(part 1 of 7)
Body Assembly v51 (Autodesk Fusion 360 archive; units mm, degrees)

design "half proto board"
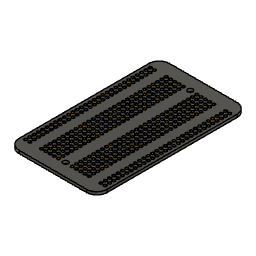
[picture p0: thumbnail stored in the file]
sketch "Sketch1" plane through (0, 0, 0) normal (0, 0, 1) x axis (1, 0, 0)
  line L1 (-26.05, -44.5) -> (26.05, -44.5)
  line L2 (-26.05, 44.5) -> (-26.05, -44.5)
  line L3 (26.05, 44.5) -> (-26.05, 44.5)
  line L4 (26.05, -44.5) -> (26.05, 44.5)
  line L5 (-26.05, 44.5) -> (26.05, -44.5)
  line L6 (26.05, 44.5) -> (-26.05, -44.5)
  line L7 (0, 44.5) -> (0, -44.5)
  line L8 (26.05, 0) -> (0, 0)
  line L9 (23.55, 44.5) -> (23.55, -44.5)
  line L10 (21.05, 44.5) -> (21.05, -44.5)
  line L11 (14.05, 44.5) -> (14.05, -44.5)
  circle C1 centre (0, -36.85) radius 1.5
  circle C2 centre (0, 36.85) radius 1.5
  circle C3 centre (23.55, -37) radius 0.65
  circle C4 centre (21.05, -37) radius 0.65
  circle C5 centre (21.05, -37) radius 0.85
  circle C6 centre (23.55, -37) radius 0.85
  circle C7 centre (14.05, -37) radius 0.65
  circle C8 centre (14.05, -37) radius 0.85
  point P6 (0, 0)
  point P1 (0, 0)
  point P7 (0, -44.5)
  point P8 (0, 44.5)
  point P9 (0, -36.85)
  point P10 (0, 0)
  point P11 (26.05, 0)
  point P13 (23.55, -44.5)
  point P14 (23.55, 44.5)
  point P15 (21.05, -44.5)
  point P16 (21.05, 44.5)
  point P17 (14.05, -44.5)
  point P18 (14.05, 44.5)
  point P19 (23.55, -37)
  point P20 (21.05, -37)
  point P23 (14.05, -37)
  point P2 (26.05, -44.5)
  point P5 (26.05, 44.5)
  horizontal L1
  perpendicular L1 L2
  parallel L1 L3
  parallel L2 L4
  coincident L5 P6
  coincident L6 P6
  coincident P1 P6
  midpoint L1 P7
  midpoint L3 P8
  coincident L7 P9
  coincident P1 P10
  midpoint L4 P11
  symmetric C1 L8 C2
  coincident L1 P13
  coincident L3 P14
  perpendicular L3 L9
  coincident L1 P15
  coincident L3 P16
  perpendicular L3 L10
  coincident L1 P17
  coincident L3 P18
  perpendicular L3 L11
  coincident L9 P19
  coincident L10 P20
  coincident L11 P23
  dimension "d1" distance P2 P5 = 89
  dimension "d2" distance L2 L4 = 52.1
  dimension "d3" diameter C1 = 3
  dimension "d4" distance P7 P9 = 7.65
  dimension "d9" distance L4 L9 = 2.5
  dimension "d10" distance L4 L10 = 5
  dimension "d11" distance L1 P20 = 7.5
  dimension "d12" distance L1 P19 = 7.5
  dimension "d13" diameter C3 = 1.3
  dimension "d14" diameter C4 = 1.3
  dimension "d15" = 0.2
  dimension "d16" = 0.2
  dimension "d17" distance L4 L11 = 12
  dimension "d18" diameter C7 = 1.3
  dimension "d19" = 0.2
  dimension "d20" distance L1 P23 = 7.5
extrude "Extrude1" new body sketch "Sketch1" profile of L1 L2 L3 L4 C1 C2 C3 C4 C5 C6 C7 C8 against normal blind 1.65
fillet "Fillet1" radius 6.1
extrude "Extrude2" cut sketch "Sketch1" profile of C3 C4 C5 C6 C7 C8 against normal blind 4
extrude "Extrude3" new body sketch "Sketch1" profile of C3 C4 C5 C6 C7 C8 against normal blind 1.65
rectangular_pattern "R-Pattern1" uSpaceDistance 2.5 vSpaceDistance 0
rectangular_pattern "R-Pattern2" uSpaceDistance -2.5 vSpaceDistance 0
copy_paste_bodies "CutPasteBodies1"
rectangular_pattern "R-Pattern3" countU 30 uSpaceDistance 73.7 vSpaceDistance 0
split "Split1"
remove_body "RemoveBody8"
mirror "Mirror1" mirrorStitchTolerance 0.1
rectangular_pattern "R-Pattern2" countU 30 uSpaceDistance -73.7 vSpaceDistance 0
mirror "Mirror1" mirrorStitchTolerance 0.1
component_from_bodies "Body->Comp1"
copy_paste "CutPaste"
component_from_bodies "Body->Comp1"
copy_paste_bodies "CutPasteBodies1"
as_built_joint "As-built1"
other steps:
base_feature "Base Feature1"
base_feature "Base Feature1"
base_feature "Base Feature1"
base_feature "Base Feature2"
create_component "CreateComponent1"
remove_body "RemoveBody1"
remove_body "RemoveBody2"
remove_body "RemoveBody3"
remove_body "RemoveBody4"
remove_body "RemoveBody5"
remove_body "RemoveBody6"
remove_body "RemoveBody7"
create_component "CreateComponent2"
remove_body "RemoveBody9"
remove_instance "RemoveInstance1"
create_component "CreateComponent1"
remove_body "RemoveBody1"
remove_body "RemoveBody2"
remove_body "RemoveBody3"
remove_body "RemoveBody4"
remove_body "RemoveBody5"
remove_body "RemoveBody6"
remove_body "RemoveBody7"
remove_body "RemoveBody8"
remove_body "RemoveBody9"
remove_body "RemoveBody10"
remove_body "RemoveBody11"
remove_body "RemoveBody12"
remove_body "RemoveBody13"
remove_body "RemoveBody14"
remove_body "RemoveBody15"
remove_body "RemoveBody16"
remove_body "RemoveBody17"
remove_body "RemoveBody18"
remove_body "RemoveBody19"
remove_body "RemoveBody20"
remove_body "RemoveBody21"
remove_body "RemoveBody22"
remove_body "RemoveBody23"
remove_body "RemoveBody24"
remove_body "RemoveBody25"
remove_body "RemoveBody26"
remove_body "RemoveBody27"
remove_body "RemoveBody28"
remove_body "RemoveBody29"
remove_body "RemoveBody30"
remove_body "RemoveBody31"
remove_body "RemoveBody32"
remove_body "RemoveBody33"
remove_body "RemoveBody34"
remove_body "RemoveBody35"
remove_body "RemoveBody36"
remove_body "RemoveBody37"
remove_body "RemoveBody38"
remove_body "RemoveBody39"
remove_body "RemoveBody40"
remove_body "RemoveBody41"
remove_body "RemoveBody42"
remove_body "RemoveBody43"
remove_body "RemoveBody44"
remove_body "RemoveBody45"
remove_body "RemoveBody46"
remove_body "RemoveBody47"
remove_body "RemoveBody48"
remove_body "RemoveBody49"
remove_body "RemoveBody50"
remove_body "RemoveBody51"
remove_body "RemoveBody52"
remove_body "RemoveBody53"
remove_body "RemoveBody54"
remove_body "RemoveBody55"
remove_body "RemoveBody56"
remove_body "RemoveBody57"
remove_body "RemoveBody58"
remove_body "RemoveBody59"
remove_body "RemoveBody60"
remove_body "RemoveBody61"
remove_body "RemoveBody62"
remove_body "RemoveBody63"
remove_body "RemoveBody64"
remove_body "RemoveBody65"
remove_body "RemoveBody66"
remove_body "RemoveBody67"
remove_body "RemoveBody68"
remove_body "RemoveBody69"
remove_body "RemoveBody70"
remove_body "RemoveBody71"
remove_body "RemoveBody72"
remove_body "RemoveBody73"
remove_body "RemoveBody74"
remove_body "RemoveBody75"
remove_body "RemoveBody76"
remove_body "RemoveBody77"
remove_body "RemoveBody78"
remove_body "RemoveBody79"
remove_body "RemoveBody80"
remove_body "RemoveBody81"
remove_body "RemoveBody82"
remove_body "RemoveBody83"
remove_body "RemoveBody84"
remove_body "RemoveBody85"
remove_body "RemoveBody86"
remove_body "RemoveBody87"
remove_body "RemoveBody88"
remove_body "RemoveBody89"
remove_body "RemoveBody90"
remove_body "RemoveBody91"
remove_body "RemoveBody92"
remove_body "RemoveBody93"
remove_body "RemoveBody94"
remove_body "RemoveBody95"
remove_body "RemoveBody96"
remove_body "RemoveBody97"
remove_body "RemoveBody98"
remove_body "RemoveBody99"
remove_body "RemoveBody100"
remove_body "RemoveBody101"
remove_body "RemoveBody102"
remove_body "RemoveBody103"
remove_body "RemoveBody104"
remove_body "RemoveBody105"
remove_body "RemoveBody106"
remove_body "RemoveBody107"
remove_body "RemoveBody108"
remove_body "RemoveBody109"
remove_body "RemoveBody110"
remove_body "RemoveBody111"
remove_body "RemoveBody112"
remove_body "RemoveBody113"
remove_body "RemoveBody114"
remove_body "RemoveBody115"
remove_body "RemoveBody116"
remove_body "RemoveBody117"
remove_body "RemoveBody118"
remove_body "RemoveBody119"
remove_body "RemoveBody120"
remove_body "RemoveBody121"
remove_body "RemoveBody122"
remove_body "RemoveBody123"
remove_body "RemoveBody124"
remove_body "RemoveBody125"
remove_body "RemoveBody126"
remove_body "RemoveBody127"
remove_body "RemoveBody128"
remove_body "RemoveBody129"
remove_body "RemoveBody130"
remove_body "RemoveBody131"
remove_body "RemoveBody132"
remove_body "RemoveBody133"
remove_body "RemoveBody134"
remove_body "RemoveBody135"
remove_body "RemoveBody136"
remove_body "RemoveBody137"
remove_body "RemoveBody138"
remove_body "RemoveBody139"
remove_body "RemoveBody140"
remove_body "RemoveBody141"
remove_body "RemoveBody142"
remove_body "RemoveBody143"
remove_body "RemoveBody144"
remove_body "RemoveBody145"
remove_body "RemoveBody146"
remove_body "RemoveBody147"
remove_body "RemoveBody148"
remove_body "RemoveBody149"
remove_body "RemoveBody150"
remove_body "RemoveBody151"
remove_body "RemoveBody152"
remove_body "RemoveBody153"
remove_body "RemoveBody154"
remove_body "RemoveBody155"
remove_body "RemoveBody156"
remove_body "RemoveBody157"
remove_body "RemoveBody158"
remove_body "RemoveBody159"
remove_body "RemoveBody160"
remove_body "RemoveBody161"
remove_body "RemoveBody162"
remove_body "RemoveBody163"
remove_body "RemoveBody164"
remove_body "RemoveBody165"
remove_body "RemoveBody166"
remove_body "RemoveBody167"
remove_body "RemoveBody168"
remove_body "RemoveBody169"
remove_body "RemoveBody170"
remove_body "RemoveBody171"
remove_body "RemoveBody172"
remove_body "RemoveBody173"
remove_body "RemoveBody174"
remove_body "RemoveBody175"
remove_body "RemoveBody176"
remove_body "RemoveBody177"
remove_body "RemoveBody178"
remove_body "RemoveBody179"
remove_body "RemoveBody180"
remove_body "RemoveBody181"
remove_body "RemoveBody182"
remove_body "RemoveBody183"
remove_body "RemoveBody184"
remove_body "RemoveBody185"
remove_body "RemoveBody186"
remove_body "RemoveBody187"
remove_body "RemoveBody188"
remove_body "RemoveBody189"
remove_body "RemoveBody190"
remove_body "RemoveBody191"
remove_body "RemoveBody192"
remove_body "RemoveBody193"
remove_body "RemoveBody194"
remove_body "RemoveBody195"
remove_body "RemoveBody196"
remove_body "RemoveBody197"
remove_body "RemoveBody198"
remove_body "RemoveBody199"
remove_body "RemoveBody200"
remove_body "RemoveBody201"
remove_body "RemoveBody202"
remove_body "RemoveBody203"
remove_body "RemoveBody204"
remove_body "RemoveBody205"
remove_body "RemoveBody206"
remove_body "RemoveBody207"
remove_body "RemoveBody208"
remove_body "RemoveBody209"
remove_body "RemoveBody210"
remove_body "RemoveBody211"
remove_body "RemoveBody212"
remove_body "RemoveBody213"
remove_body "RemoveBody214"
remove_body "RemoveBody215"
remove_body "RemoveBody216"
remove_body "RemoveBody217"
remove_body "RemoveBody218"
remove_body "RemoveBody219"
remove_body "RemoveBody220"
remove_body "RemoveBody221"
remove_body "RemoveBody222"
remove_body "RemoveBody223"
remove_body "RemoveBody224"
remove_body "RemoveBody225"
remove_body "RemoveBody226"
remove_body "RemoveBody227"
remove_body "RemoveBody228"
remove_body "RemoveBody229"
remove_body "RemoveBody230"
remove_body "RemoveBody231"
remove_body "RemoveBody232"
remove_body "RemoveBody233"
remove_body "RemoveBody234"
remove_body "RemoveBody235"
remove_body "RemoveBody236"
remove_body "RemoveBody237"
remove_body "RemoveBody238"
remove_body "RemoveBody239"
remove_body "RemoveBody240"
remove_body "RemoveBody241"
remove_body "RemoveBody242"
remove_body "RemoveBody243"
remove_body "RemoveBody244"
remove_body "RemoveBody245"
remove_body "RemoveBody246"
remove_body "RemoveBody247"
remove_body "RemoveBody248"
remove_body "RemoveBody249"
remove_body "RemoveBody250"
remove_body "RemoveBody251"
remove_body "RemoveBody252"
remove_body "RemoveBody253"
remove_body "RemoveBody254"
remove_body "RemoveBody255"
remove_body "RemoveBody256"
remove_body "RemoveBody257"
remove_body "RemoveBody258"
remove_body "RemoveBody259"
remove_body "RemoveBody260"
remove_body "RemoveBody261"
remove_body "RemoveBody262"
remove_body "RemoveBody263"
remove_body "RemoveBody264"
remove_body "RemoveBody265"
remove_body "RemoveBody266"
remove_body "RemoveBody267"
remove_body "RemoveBody268"
remove_body "RemoveBody269"
remove_body "RemoveBody270"
remove_body "RemoveBody271"
remove_body "RemoveBody272"
remove_body "RemoveBody273"
remove_body "RemoveBody274"
remove_body "RemoveBody275"
remove_body "RemoveBody276"
remove_body "RemoveBody277"
remove_body "RemoveBody278"
remove_body "RemoveBody279"
remove_body "RemoveBody280"
remove_body "RemoveBody281"
remove_body "RemoveBody282"
remove_body "RemoveBody283"
remove_body "RemoveBody284"
remove_body "RemoveBody285"
remove_body "RemoveBody286"
remove_body "RemoveBody287"
remove_body "RemoveBody288"
remove_body "RemoveBody289"
remove_body "RemoveBody290"
remove_body "RemoveBody291"
remove_body "RemoveBody292"
remove_body "RemoveBody293"
remove_body "RemoveBody294"
remove_body "RemoveBody295"
remove_body "RemoveBody296"
remove_body "RemoveBody297"
remove_body "RemoveBody298"
remove_body "RemoveBody299"
remove_body "RemoveBody300"
remove_body "RemoveBody301"
remove_body "RemoveBody302"
remove_body "RemoveBody303"
remove_body "RemoveBody304"
remove_body "RemoveBody305"
remove_body "RemoveBody306"
remove_body "RemoveBody307"
remove_body "RemoveBody308"
remove_body "RemoveBody309"
remove_body "RemoveBody310"
remove_body "RemoveBody311"
remove_body "RemoveBody312"
remove_body "RemoveBody313"
remove_body "RemoveBody314"
remove_body "RemoveBody315"
remove_body "RemoveBody316"
remove_body "RemoveBody317"
remove_body "RemoveBody318"
remove_body "RemoveBody319"
remove_body "RemoveBody320"
remove_body "RemoveBody321"
remove_body "RemoveBody322"
remove_body "RemoveBody323"
remove_body "RemoveBody324"
remove_body "RemoveBody325"
remove_body "RemoveBody326"
remove_body "RemoveBody327"
remove_body "RemoveBody328"
remove_body "RemoveBody329"
remove_body "RemoveBody330"
remove_body "RemoveBody331"
remove_body "RemoveBody332"
remove_body "RemoveBody333"
remove_body "RemoveBody334"
remove_body "RemoveBody335"
remove_body "RemoveBody336"
remove_body "RemoveBody337"
remove_body "RemoveBody338"
remove_body "RemoveBody339"
remove_body "RemoveBody340"
remove_body "RemoveBody341"
remove_body "RemoveBody342"
remove_body "RemoveBody343"
remove_body "RemoveBody344"
remove_body "RemoveBody345"
remove_body "RemoveBody346"
remove_body "RemoveBody347"
remove_body "RemoveBody348"
remove_body "RemoveBody349"
remove_body "RemoveBody350"
remove_body "RemoveBody351"
remove_body "RemoveBody352"
remove_body "RemoveBody353"
remove_body "RemoveBody354"
remove_body "RemoveBody355"
remove_body "RemoveBody356"
remove_body "RemoveBody357"
remove_body "RemoveBody358"
remove_body "RemoveBody359"
remove_body "RemoveBody360"
remove_body "RemoveBody361"
remove_body "RemoveBody362"
remove_body "RemoveBody363"
remove_body "RemoveBody364"
remove_body "RemoveBody365"
remove_body "RemoveBody366"
remove_body "RemoveBody367"
remove_body "RemoveBody368"
remove_body "RemoveBody369"
remove_body "RemoveBody370"
remove_body "RemoveBody371"
remove_body "RemoveBody372"
remove_body "RemoveBody373"
remove_body "RemoveBody374"
remove_body "RemoveBody375"
remove_body "RemoveBody376"
remove_body "RemoveBody377"
remove_body "RemoveBody378"
remove_body "RemoveBody379"
remove_body "RemoveBody380"
remove_body "RemoveBody381"
remove_body "RemoveBody382"
remove_body "RemoveBody383"
remove_body "RemoveBody384"
remove_body "RemoveBody385"
remove_body "RemoveBody386"
remove_body "RemoveBody387"
remove_body "RemoveBody388"
remove_body "RemoveBody389"
remove_body "RemoveBody390"
remove_body "RemoveBody391"
remove_body "RemoveBody392"
remove_body "RemoveBody393"
remove_body "RemoveBody394"
remove_body "RemoveBody395"
remove_body "RemoveBody396"
remove_body "RemoveBody397"
remove_body "RemoveBody398"
remove_body "RemoveBody399"
remove_body "RemoveBody400"
remove_body "RemoveBody401"
remove_body "RemoveBody402"
remove_body "RemoveBody403"
remove_body "RemoveBody404"
remove_body "RemoveBody405"
remove_body "RemoveBody406"
remove_body "RemoveBody407"
remove_body "RemoveBody408"
remove_body "RemoveBody409"
remove_body "RemoveBody410"
remove_body "RemoveBody411"
remove_body "RemoveBody412"
remove_body "RemoveBody413"
remove_body "RemoveBody414"
remove_body "RemoveBody415"
remove_body "RemoveBody416"
remove_body "RemoveBody417"
remove_body "RemoveBody418"
remove_body "RemoveBody419"
remove_body "RemoveBody420"

design "BTS790 Motor Driver"
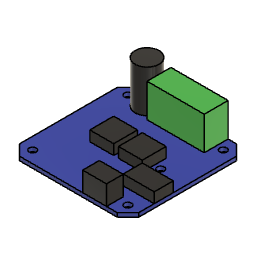
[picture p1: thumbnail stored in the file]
sketch "Sketch1" plane through (0, 0, 0) normal (0, 0, 1) x axis (1, 0, 0)
  line L1 (-25, -25) -> (25, -25)
  line L2 (-25, 25) -> (-25, -25)
  line L3 (25, 25) -> (-25, 25)
  line L4 (25, -25) -> (25, 25)
  line L5 (-25, 25) -> (25, -25)
  line L6 (25, 25) -> (-25, -25)
  line L7 (17, 25) -> (-7, 25)
  line L8 (17, 15) -> (17, 25)
  line L9 (-7, 15) -> (17, 15)
  line L10 (-7, 25) -> (-7, 15)
  line L11 (6, -25) -> (16, -25)
  line L12 (6, -18) -> (6, -25)
  line L13 (16, -18) -> (6, -18)
  line L14 (16, -25) -> (16, -18)
  line L15 (1, -5) -> (11, -5)
  line L16 (1, 5) -> (1, -5)
  line L17 (11, 5) -> (1, 5)
  line L18 (11, -5) -> (11, 5)
  line L19 (1, 5) -> (11, -5)
  line L20 (11, 5) -> (1, -5)
  line L21 (25, 0) -> (0, 0)
  line L22 (0, -25) -> (0, 0)
  line L23 (-11, 5) -> (-1, 5)
  line L24 (-11, -5) -> (-11, 5)
  line L25 (-1, 5) -> (-1, -5)
  line L26 (-1, -5) -> (-11, -5)
  line L27 (25, -6) -> (12, -6)
  line L28 (25, -14) -> (25, -6)
  line L29 (12, -14) -> (25, -14)
  line L30 (12, -6) -> (12, -14)
  line L31 (25, 0) -> (-25, 0)
  circle C1 centre (-12, 20) radius 5
  circle C2 centre (13.75, 0) radius 1.5
  circle C3 centre (-13.75, 0) radius 1.5
  circle C4 centre (-20, 20) radius 1.5
  circle C5 centre (-20, -20) radius 1.5
  point P6 (0, 0)
  point P1 (0, 0)
  point P7 (-7, 25)
  point P12 (16, -25)
  point P21 (6, 0)
  point P22 (0, 0)
  point P23 (25, 0)
  point P24 (0, 0)
  point P25 (0, -25)
  point P17 (11, -5)
  point P28 (-11, -5)
  point P18 (1, -5)
  point P29 (-1, -5)
  point P19 (1, 5)
  point P26 (-1, 5)
  point P20 (11, 5)
  point P27 (-11, 5)
  point P5 (25, 25)
  point P35 (-20, 20)
  point P16 (13.75, 0)
  point P36 (-20, -20)
  point P37 (-25, 0)
  point P4 (-25, 25)
  point P31 (12, -6)
  point P32 (25, -6)
  horizontal L1
  perpendicular L1 L2
  parallel L1 L3
  parallel L2 L4
  coincident L5 P6
  coincident L6 P6
  coincident P1 P6
  horizontal L7
  vertical L8
  horizontal L9
  vertical L10
  coincident L3 P7
  tangent L10 C1
  tangent L3 C1
  horizontal L11
  vertical L12
  horizontal L13
  vertical L14
  coincident L1 P12
  horizontal L15
  perpendicular L15 L16
  parallel L15 L17
  parallel L16 L18
  coincident L19 P21
  coincident L20 P21
  coincident P1 P22
  midpoint L4 P23
  coincident P21 L21
  coincident P6 P24
  midpoint L1 P25
  symmetric C2 L22 C3
  symmetric P17 L22 P28
  symmetric P18 L22 P29
  symmetric P19 L22 P26
  symmetric P20 L22 P27
  horizontal L27
  vertical L28
  horizontal L29
  vertical L30
  coincident P5 L28
  coincident L5 P35
  coincident P16 L21
  coincident L6 P36
  midpoint L2 P37
  symmetric C4 C5 L31
  dimension "d1" distance P4 P5 = 50
  dimension "d2" distance L1 L3 = 50
  dimension "d3" distance L4 L8 = 8
  dimension "d4" distance L2 L10 = 18
  dimension "d5" distance L3 L9 = 10
  dimension "d6" diameter C1 = 10
  dimension "d7" distance L4 L14 = 9
  dimension "d8" distance L12 L14 = 10
  dimension "d9" distance L1 L13 = 7
  dimension "d11" distance P1 P16 = 13.75 (= "( 27.5 / 2 ) * 1 mm")
  dimension "d12" diameter C2 = 3
  dimension "d13" distance P19 P20 = 10
  dimension "d14" distance P17 P20 = 10
  dimension "d15" distance P1 P21 = 6
  dimension "d17" distance P31 P32 = 13
  dimension "d18" distance L13 L29 = 4
  dimension "d19" distance L27 L29 = 8
  dimension "d33" diameter C4 = 3
  dimension "d34" distance P35 P36 = 40 (= "37 mm + 3 mm")
extrude "Extrude1" new body sketch "Sketch1" profile of L1 L2 L3 L4 L7 L8 L9 L10 C1 L11 L12 L13 L14 C2 L15 L16 L17 L18 L23 L24 L25 L26 C3 L27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 against normal blind 1.65
extrude "Extrude2" new body sketch "Sketch1" profile of C1 along normal blind 17.65
extrude "Extrude3" new body sketch "Sketch1" profile of L3 L7 L8 L9 L10 along normal blind 14
extrude "Extrude4" new body sketch "Sketch1" profile of L15 L16 L17 L18 L23 L24 L25 L26 along normal blind 4.3
extrude "Extrude5" new body sketch "Sketch1" profile of L4 L27 L28 L29 L30 along normal blind 4.3
extrude "Extrude6" new body sketch "Sketch1" profile of L1 L11 L12 L13 L14 along normal blind 8.2
chamfer "Chamfer1" distance 4.5
component_from_bodies "Body->Comp"
copy_paste_bodies "CutPasteBodies"
extrude "Extrude1" cut sketch "Sketch1" profile of C4 C5 against normal blind 17
mirror "Mirror1" mirrorStitchTolerance 0.1
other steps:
base_feature "Base Feature1"
base_feature "Base Feature2"
create_component "CreateComponent1"
remove_body "RemoveBody1"
remove_body "RemoveBody2"
remove_body "RemoveBody3"
remove_body "RemoveBody4"
remove_body "RemoveBody5"
remove_body "RemoveBody6"
remove_body "RemoveBody7"

design "USB host shield"
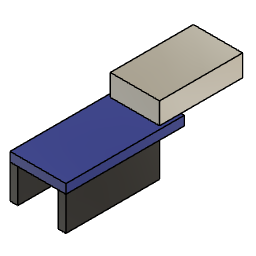
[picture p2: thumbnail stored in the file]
sketch "Sketch1" plane through (0, 0, 0) normal (0, 0, 1) x axis (1, 0, 0)
  line L1 (-9.075, -19.25) -> (9.075, -19.25)
  line L2 (-9.075, 19.25) -> (-9.075, -19.25)
  line L3 (9.075, 19.25) -> (-9.075, 19.25)
  line L4 (9.075, -19.25) -> (9.075, 19.25)
  line L5 (-9.075, 19.25) -> (9.075, -19.25)
  line L6 (9.075, 19.25) -> (-9.075, -19.25)
  line L7 (6.575, -19.25) -> (9.075, -19.25)
  line L8 (6.575, 11.2) -> (6.575, -19.25)
  line L9 (9.075, 11.2) -> (6.575, 11.2)
  line L10 (9.075, -19.25) -> (9.075, 11.2)
  line L11 (0, -19.25) -> (0, 19.25)
  line L12 (-6.575, -19.25) -> (-9.075, -19.25)
  line L13 (-9.075, 11.2) -> (-6.575, 11.2)
  line L14 (-9.075, -19.25) -> (-9.075, 11.2)
  line L15 (-6.575, 11.2) -> (-6.575, -19.25)
  line L16 (-8, 39.25) -> (8, 39.25)
  line L17 (-8, 12.25) -> (-8, 39.25)
  line L18 (8, 12.25) -> (-8, 12.25)
  line L19 (8, 39.25) -> (8, 12.25)
  line L20 (-8, 12.25) -> (8, 39.25)
  line L21 (8, 12.25) -> (-8, 39.25)
  point P6 (0, 0)
  point P1 (0, 0)
  point P10 (0, 19.25)
  point P11 (0, -19.25)
  point P2 (9.075, -19.25)
  point P12 (-9.075, -19.25)
  point P7 (6.575, -19.25)
  point P13 (-6.575, -19.25)
  point P8 (6.575, 11.2)
  point P14 (-6.575, 11.2)
  point P9 (9.075, 11.2)
  point P15 (-9.075, 11.2)
  point P20 (0, 25.75)
  point P4 (-9.075, 19.25)
  point P5 (9.075, 19.25)
  point P16 (8, 39.25)
  point P19 (8, 12.25)
  point P17 (-8, 39.25)
  horizontal L1
  perpendicular L1 L2
  parallel L1 L3
  parallel L2 L4
  coincident L5 P6
  coincident L6 P6
  coincident P1 P6
  horizontal L7
  vertical L8
  horizontal L9
  vertical L10
  midpoint L3 P10
  midpoint L1 P11
  symmetric P2 L11 P12
  symmetric P7 L11 P13
  symmetric P8 L11 P14
  symmetric P9 L11 P15
  horizontal L16
  perpendicular L16 L17
  parallel L16 L18
  parallel L17 L19
  coincident L20 P20
  coincident L21 P20
  coincident L11 P20
  dimension "d1" distance P4 P5 = 18.15
  dimension "d2" distance P2 P5 = 38.5
  dimension "d3" distance P7 P8 = 30.45
  dimension "d4" distance L4 L8 = 2.5
  dimension "d5" distance L3 L18 = 7
  dimension "d6" distance P16 P19 = 27
  dimension "d7" distance P16 P17 = 16
extrude "Extrude1" new body sketch "Sketch1" profile of L1 L2 L3 L4 L7 L8 L9 L10 L12 L13 L14 L15 L17 L18 L19 along normal blind 3
extrude "Extrude2" sketch "Sketch1" profile of L3 L16 L17 L18 L19 blind 7
extrude "Extrude3" new body sketch "Sketch1" profile of L1 L2 L4 L7 L8 L9 L10 L12 L13 L14 L15 against normal blind 11

design "3s 8000mah LIPO battery"
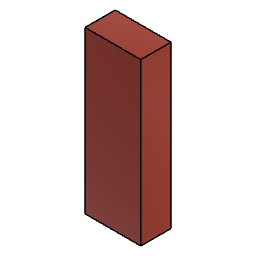
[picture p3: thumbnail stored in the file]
sketch "Sketch1" plane through (0, 0, 0) normal (0, 0, 1) x axis (1, 0, 0)
  line L1 (-24, -13) -> (24, -13)
  line L2 (-24, 13) -> (-24, -13)
  line L3 (24, 13) -> (-24, 13)
  line L4 (24, -13) -> (24, 13)
  line L5 (-24, 13) -> (24, -13)
  line L6 (24, 13) -> (-24, -13)
  point P6 (0, 0)
  point P1 (0, 0)
  point P2 (24, -13)
  point P5 (24, 13)
  point P3 (-24, -13)
  horizontal L1
  perpendicular L1 L2
  parallel L1 L3
  parallel L2 L4
  coincident L5 P6
  coincident L6 P6
  coincident P1 P6
  dimension "d1" distance P2 P5 = 26
  dimension "d2" distance P2 P3 = 48
extrude "Extrude1" new body sketch "Sketch1" profile of L1 L2 L3 L4 along normal blind 139

design "Teensy 4.1"
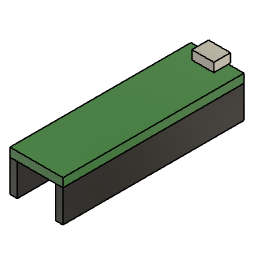
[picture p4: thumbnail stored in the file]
sketch "Sketch1" plane through (0, 0, 0) normal (0, 0, 1) x axis (1, 0, 0)
  line L1 (-9.075, -31) -> (9.075, -31)
  line L2 (-9.075, 31) -> (-9.075, -31)
  line L3 (9.075, 31) -> (-9.075, 31)
  line L4 (9.075, -31) -> (9.075, 31)
  line L5 (-9.075, 31) -> (9.075, -31)
  line L6 (9.075, 31) -> (-9.075, -31)
  line L7 (0, -31) -> (0, 31)
  line L8 (-3.75, 26) -> (3.75, 26)
  line L9 (-3.75, 31.7) -> (-3.75, 26)
  line L10 (3.75, 31.7) -> (-3.75, 31.7)
  line L11 (3.75, 26) -> (3.75, 31.7)
  line L12 (-3.75, 31.7) -> (3.75, 26)
  line L13 (3.75, 31.7) -> (-3.75, 26)
  line L14 (6.575, 31) -> (9.075, 31)
  line L15 (6.575, -31) -> (6.575, 31)
  line L16 (9.075, -31) -> (6.575, -31)
  line L17 (9.075, 31) -> (9.075, -31)
  line L18 (-6.575, 31) -> (-9.075, 31)
  line L19 (-6.575, -31) -> (-6.575, 31)
  line L20 (-9.075, -31) -> (-6.575, -31)
  line L21 (-9.075, 31) -> (-9.075, -31)
  point P6 (0, 0)
  point P1 (0, 0)
  point P7 (0, 31)
  point P8 (0, -31)
  point P13 (0, 28.85)
  point P15 (6.575, -31)
  point P18 (-6.575, -31)
  point P4 (-9.075, 31)
  point P5 (9.075, 31)
  point P2 (9.075, -31)
  point P9 (3.75, 26)
  point P10 (-3.75, 26)
  horizontal L1
  perpendicular L1 L2
  parallel L1 L3
  parallel L2 L4
  coincident L5 P6
  coincident L6 P6
  coincident P1 P6
  midpoint L3 P7
  midpoint L1 P8
  horizontal L8
  perpendicular L8 L9
  parallel L8 L10
  parallel L9 L11
  coincident L12 P13
  coincident L13 P13
  coincident L7 P13
  horizontal L14
  vertical L15
  horizontal L16
  vertical L17
  coincident L1 P15
  horizontal L18
  vertical L19
  horizontal L20
  vertical L21
  coincident L1 P18
  dimension "d1" distance P4 P5 = 18.15
  dimension "d2" distance P2 P5 = 62
  dimension "d3" distance L3 L10 = 0.7
  dimension "d4" distance L8 L10 = 5.7
  dimension "d5" distance P9 P10 = 7.5
  dimension "d6" distance L19 L21 = 2.5
  dimension "d7" distance L4 L15 = 2.5
extrude "Extrude1" new body sketch "Sketch1" profile of L1 L2 L3 L4 L8 L9 L11 L14 L15 L16 L17 L18 L19 L20 L21 along normal blind 3
extrude "Extrude2" new body sketch "Sketch1" profile of L1 L2 L3 L4 L14 L15 L16 L17 L18 L19 L20 L21 against normal blind 11
extrude "Extrude3" sketch "Sketch1" profile of L3 L8 L9 L10 L11 blind 3.07

design "Leg Assembly" references "Servo Actuator 2.0"
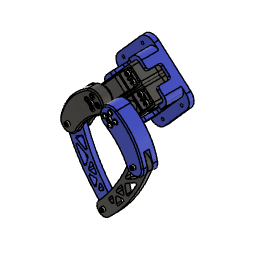
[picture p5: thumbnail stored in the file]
parameter "gapfit1" = 1 comment "gap on either side of the link 1 and 2 notch to accomodate link 3 and 4"
parameter "gapfit2" = 0.5 comment "gap between link 3 and 4"
parameter "gapfit3" = 0.5 comment "offset of space in the servos holder"
parameter "m3_diam" = 3.5 (= "3 mm + ( 0.5 mm )") comment "diameter used for m3 screw holes"
parameter "m3_locknut_width" = 5.9 (= "5.4 mm + ( 0.5 mm )") comment "lock nut width"
component_insert "Component Insert1"
component_insert "Component Insert2"
position "Position1"
position "Position2"
position "Position3"
base_feature "Base Feature1"
base_feature "Base Feature1"
base_feature "Base Feature1"
base_feature "Base Feature1"
extrude "Extrude1" add of existing geometry blind 3.556
extrude "Extrude2" add of existing geometry blind 1
sketch "Sketch1" plane through (0, 0, 13.9918) normal (0, 0, -1) x axis (1, 0, 0)
  circle C1 centre (0, -10.25) radius 4
  circle C2 centre (0, -10.25) radius 8.7625
  dimension "d5" = 4.7625
extrude "Extrude1" new body sketch "Sketch1" along normal blind 5.675 (= "0.125 in + 2.5 mm")
extrude "Extrude3" add of existing geometry blind 3.175
combine "Combine1"
extrude "Extrude2" cut of existing geometry blind -4.7
sketch "Sketch2" plane through (0, 0, 24.9956) normal (0, 0, 1) x axis (-1, 0, 0)
  line L1 (0.8395, -12.0586) -> (1.9866, -10.4203)
  line L2 (-1.9866, -10.0797) -> (0.8395, -12.0586)
  line L3 (-0.8395, -8.4414) -> (-1.9866, -10.0797)
  line L4 (1.9866, -10.4203) -> (-0.8395, -8.4414)
  line L5 (-1.9866, -10.0797) -> (-0.8395, -8.4414)
  line L6 (0.8395, -12.0586) -> (-1.9866, -10.0797)
  line L7 (1.9866, -10.4203) -> (0.8395, -12.0586)
  line L8 (-0.8395, -8.4414) -> (1.9866, -10.4203)
  circle C1 centre (0, -10.25) radius 4
split "Split1"
copy_paste_bodies "CutPasteBodies1"
copy_paste_bodies "CutPasteBodies1"
component_from_bodies "Body->Comp1"
extrude "Extrude3" new body of existing geometry blind 2.5
delete_face "DeleteFace1"
component_from_bodies "Body->Comp1"
copy_paste "CutPaste1"
sketch "Sketch1" plane through (0, 0, 0) normal (0, 0, 1) x axis (1, 0, 0)
  line L1 (-7.25, -8.75) -> (7.25, -8.75)
  line L2 (-7.25, 8.75) -> (-7.25, -8.75)
  line L3 (7.25, 8.75) -> (-7.25, 8.75)
  line L4 (7.25, -8.75) -> (7.25, 8.75)
  line L5 (-7.25, 8.75) -> (7.25, -8.75)
  line L6 (7.25, 8.75) -> (-7.25, -8.75)
  line L7 (0, 8.75) -> (0, -8.75)
  line L8 (-2.5, -2.35) -> (2.5, -2.35)
  line L9 (-2.5, 1.45) -> (-2.5, -2.35)
  line L10 (2.5, 1.45) -> (-2.5, 1.45)
  line L11 (2.5, -2.35) -> (2.5, 1.45)
  line L12 (-2.5, 1.45) -> (2.5, -2.35)
  line L13 (2.5, 1.45) -> (-2.5, -2.35)
  line L14 (7.25, -0.45) -> (-7.25, -0.45)
  line L15 (3.75, -8.75) -> (7.25, -5.25)
  line L16 (-3.75, -8.75) -> (-7.25, -5.25)
  arc A1 centre (0, 0.1797) radius 8.5703 clockwise from (-7.25, 4.75) to (7.25, 4.75)
  circle C1 centre (6, -0.45) radius 1.5
  circle C2 centre (-6, -0.45) radius 1.5
  point P6 (0, 0)
  point P1 (0, 0)
  point P7 (0, -8.75)
  point P8 (0, 8.75)
  point P13 (0, -0.45)
  point P14 (-7.25, -0.45)
  point P15 (7.25, -0.45)
  point P16 (7.25, 4.75)
  point P17 (-7.25, 4.75)
  point P19 (7.25, 4.75)
  point P18 (-7.25, 4.75)
  point P21 (7.25, -5.25)
  point P22 (3.75, -8.75)
  point P23 (7.25, -5.25)
  point P24 (3.75, -8.75)
  point P25 (-7.25, -5.25)
  point P26 (-3.75, -8.75)
  point P27 (6, -0.45)
  point P2 (7.25, -8.75)
  point P5 (7.25, 8.75)
  horizontal L1
  perpendicular L1 L2
  parallel L1 L3
  parallel L2 L4
  coincident L5 P6
  coincident L6 P6
  coincident P1 P6
  midpoint L1 P7
  midpoint L3 P8
  horizontal L8
  perpendicular L8 L9
  parallel L8 L10
  parallel L9 L11
  coincident L12 P13
  coincident L13 P13
  coincident L7 P13
  coincident L2 P14
  coincident L4 P15
  perpendicular L4 L14
  coincident P13 L14
  coincident L4 P16
  symmetric L7 P16 P17
  coincident P8 A1
  tangent L3 A1
  coincident P16 P19
  coincident P17 P18
  coincident L4 P21
  coincident L1 P22
  coincident P21 P23
  coincident P22 P24
  symmetric L7 P23 P25
  symmetric L7 P24 P26
  coincident L14 P27
  symmetric L7 C1 C2
  dimension "d1_1" distance P2 P5 = 17.5
  dimension "d2_1" distance L2 L4 = 14.5
  dimension "d3_1" distance L1 L8 = 6.4
  dimension "d4_1" distance L3 L10 = 7.3
  dimension "d5_1" distance L9 L11 = 5
  dimension "d6_1" distance P5 P16 = 4
  dimension "d7_1" distance P2 P21 = 3.5
  dimension "d8_1" distance P2 P22 = 3.5
  dimension "d9_1" diameter C1 = 3
  dimension "d10_1" distance L11 P27 = 3.5 (= "2 mm + 1.5 mm")
extrude "Extrude1" new body sketch "Sketch1" profile of L1 L2 L4 L8 L9 L10 L11 A1 L15 L16 C1 C2 against normal blind 1.7 named "d11_1"
extrude "Extrude2" new body sketch "Sketch1" profile of L8 L9 L10 L11 along normal blind 1.5 named "d13_1"
position "Position1"
position "Position2"
position "Position3"
position "Position4"
copy_paste "CutPaste2"
work_plane "WorkPlane1" AlongDistance -21
split "Split1"
combine "Combine1"
split "Split1"
remove_body "RemoveBody2"
extrude "Extrude1" add of existing geometry blind 2.2
extrude "Extrude2" add of existing geometry blind 1
extrude "Extrude3" cut of existing geometry blind -0.2
extrude "Extrude4" add of existing geometry blind 0.2
work_plane "WorkPlane2"
extrude "Extrude4" cut of existing geometry blind -0.2063 (= "( 2 mm - ( ( 1 / 16 ) * 1 in ) ) / -2")
extrude "Extrude5" cut of existing geometry blind -0.2063 (= "( 2 mm - ( ( 1 / 16 ) * 1 in ) ) / -2")
extrude "Extrude5" add of existing geometry blind 0.2063 (= "( 2 mm - ( ( 1 / 16 ) * 1 in ) ) / 2")
extrude "Extrude6" add of existing geometry blind 0.2063 (= "( 2 mm - ( ( 1 / 16 ) * 1 in ) ) / 2")
sketch "Sketch4" plane through (0, 0, 28) normal (0, 0, -1) x axis (1, 0, 0)
  line L1 (-1.6037, -23.3708) -> (-1.6037, 14.6292)
  line L2 (-0.9037, -30.2208) -> (-0.9037, -24.3248)
  line L3 (2.4963, -31.7208) -> (0.5963, -31.7208)
  line L4 (2.4963, -31.0175) -> (2.4963, -31.7208)
  line L5 (4.4963, -31.7208) -> (4.4963, -31.0175)
  line L6 (12.2963, -31.7208) -> (4.4963, -31.7208)
  line L7 (12.2963, -31.0175) -> (12.2963, -31.7208)
  line L8 (14.2963, -31.7208) -> (14.2963, -31.0175)
  line L9 (16.1963, -31.7208) -> (14.2963, -31.7208)
  line L10 (17.6963, -24.3248) -> (17.6963, -30.2208)
  line L11 (18.3963, 14.6292) -> (18.3963, -23.3708)
  line L12 (17.6963, 21.4792) -> (17.6963, 15.5831)
  line L13 (14.2963, 22.9792) -> (16.1963, 22.9792)
  line L14 (14.2963, 22.2758) -> (14.2963, 22.9792)
  line L15 (12.2963, 22.9792) -> (12.2963, 22.2758)
  line L16 (4.4963, 22.9792) -> (12.2963, 22.9792)
  line L17 (4.4963, 22.2758) -> (4.4963, 22.9792)
  line L18 (2.4963, 22.9792) -> (2.4963, 22.2758)
  line L19 (0.5963, 22.9792) -> (2.4963, 22.9792)
  line L20 (-0.9037, 15.5831) -> (-0.9037, 21.4792)
  line L21 (15.3963, 15.6292) -> (1.3963, 15.6292)
  line L22 (1.3963, 15.6292) -> (15.3963, 15.6292)
  line L23 (8.3963, -2.0612) -> (8.3963, 15.6292)
  line L24
  arc A1 centre (-0.6037, 14.6292) radius 1 clockwise from (-1.6037, 14.6292) to (-0.9037, 15.5831)
  arc A2 centre (-0.6037, -23.3708) radius 1 clockwise from (-0.9037, -24.3248) to (-1.6037, -23.3708)
  arc A3 centre (0.5963, -30.2208) radius 1.5 clockwise from (0.5963, -31.7208) to (-0.9037, -30.2208)
  arc A4 centre (3.4963, -29.1708) radius 2.1 clockwise from (2.4963, -31.0175) to (4.4963, -31.0175)
  arc A5 centre (13.2963, -29.1708) radius 2.1 clockwise from (12.2963, -31.0175) to (14.2963, -31.0175)
  arc A6 centre (16.1963, -30.2208) radius 1.5 clockwise from (17.6963, -30.2208) to (16.1963, -31.7208)
  arc A7 centre (17.3963, -23.3708) radius 1 clockwise from (18.3963, -23.3708) to (17.6963, -24.3248)
  arc A8 centre (17.3963, 14.6292) radius 1 clockwise from (17.6963, 15.5831) to (18.3963, 14.6292)
  arc A9 centre (16.1963, 21.4792) radius 1.5 clockwise from (16.1963, 22.9792) to (17.6963, 21.4792)
  arc A10 centre (13.2963, 20.4292) radius 2.1 clockwise from (14.2963, 22.2758) to (12.2963, 22.2758)
  arc A11 centre (3.4963, 20.4292) radius 2.1 clockwise from (4.4963, 22.2758) to (2.4963, 22.2758)
  arc A12 centre (0.5963, 21.4792) radius 1.5 clockwise from (-0.9037, 21.4792) to (0.5963, 22.9792)
  circle C1 centre (8.3963, 6.1292) radius 8.5
  point P48 (8.3963, 15.6292)
  point P50 (8.3963, 6.1292)
  midpoint L21 P48
  perpendicular L21 L23
  coincident L23 P50
  perpendicular L1 L24
  tangent C1 L24
  dimension "d32" diameter C1 = 17
  dimension "d33" distance L22 L24 = 1
extrude "Extrude4" new body sketch "Sketch4" profile of C1 along normal blind 27.9908
extrude "Extrude5" add of existing geometry blind 0.5092 (= "41.5 mm - 1.6138110236220502 in")
copy_paste_bodies "CutPasteBodies1"
sketch "Sketch5" plane through (0, 0, 28) normal (0, 0, -1) x axis (1, 0, 0)
  line L1 (-1.6037, -23.3708) -> (-1.6037, 14.6292)
  line L2 (-0.9037, -30.2208) -> (-0.9037, -24.3248)
  line L3 (2.4963, -31.7208) -> (0.5963, -31.7208)
  line L4 (2.4963, -31.0175) -> (2.4963, -31.7208)
  line L5 (4.4963, -31.7208) -> (4.4963, -31.0175)
  line L6 (12.2963, -31.7208) -> (4.4963, -31.7208)
  line L7 (12.2963, -31.0175) -> (12.2963, -31.7208)
  line L8 (14.2963, -31.7208) -> (14.2963, -31.0175)
  line L9 (16.1963, -31.7208) -> (14.2963, -31.7208)
  line L10 (17.6963, -24.3248) -> (17.6963, -30.2208)
  line L11 (18.3963, 14.6292) -> (18.3963, -23.3708)
  line L12 (17.6963, 21.4792) -> (17.6963, 15.5831)
  line L13 (14.2963, 22.9792) -> (16.1963, 22.9792)
  line L14 (14.2963, 22.2758) -> (14.2963, 22.9792)
  line L15 (12.2963, 22.9792) -> (12.2963, 22.2758)
  line L16 (4.4963, 22.9792) -> (12.2963, 22.9792)
  line L17 (4.4963, 22.2758) -> (4.4963, 22.9792)
  line L18 (2.4963, 22.9792) -> (2.4963, 22.2758)
  line L19 (0.5963, 22.9792) -> (2.4963, 22.9792)
  line L20 (-0.9037, 15.5831) -> (-0.9037, 21.4792)
  arc A1 centre (-0.6037, 14.6292) radius 1 clockwise from (-1.6037, 14.6292) to (-0.9037, 15.5831)
  arc A2 centre (-0.6037, -23.3708) radius 1 clockwise from (-0.9037, -24.3248) to (-1.6037, -23.3708)
  arc A3 centre (0.5963, -30.2208) radius 1.5 clockwise from (0.5963, -31.7208) to (-0.9037, -30.2208)
  arc A4 centre (3.4963, -29.1708) radius 2.1 clockwise from (2.4963, -31.0175) to (4.4963, -31.0175)
  arc A5 centre (13.2963, -29.1708) radius 2.1 clockwise from (12.2963, -31.0175) to (14.2963, -31.0175)
  arc A6 centre (16.1963, -30.2208) radius 1.5 clockwise from (17.6963, -30.2208) to (16.1963, -31.7208)
  arc A7 centre (17.3963, -23.3708) radius 1 clockwise from (18.3963, -23.3708) to (17.6963, -24.3248)
  arc A8 centre (17.3963, 14.6292) radius 1 clockwise from (17.6963, 15.5831) to (18.3963, 14.6292)
  arc A9 centre (16.1963, 21.4792) radius 1.5 clockwise from (16.1963, 22.9792) to (17.6963, 21.4792)
  arc A10 centre (13.2963, 20.4292) radius 2.1 clockwise from (14.2963, 22.2758) to (12.2963, 22.2758)
  arc A11 centre (3.4963, 20.4292) radius 2.1 clockwise from (4.4963, 22.2758) to (2.4963, 22.2758)
  arc A12 centre (0.5963, 21.4792) radius 1.5 clockwise from (-0.9037, 21.4792) to (0.5963, 22.9792)
split "Split1"
remove_body "RemoveBody1"
delete_face "DeleteFace1"
delete_face "DeleteFace2"
sketch "Sketch6" plane through (0, 0, 28) normal (0, 0, -1) x axis (1, 0, 0)
  line L1 (-0.9037, -24.3248) -> (17.6963, 15.5831)
  line L2 (-0.9037, 15.5831) -> (17.6963, -24.3248)
  line L3 (-0.8337, -23.6158) -> (17.6263, -23.6158)
  line L4 (-0.8337, 14.8742) -> (-0.8337, -23.6158)
  line L5 (17.6263, 14.8742) -> (-0.8337, 14.8742)
  line L6 (17.6263, -23.6158) -> (17.6263, 14.8742)
  line L7 (-0.8337, 14.8742) -> (17.6263, -23.6158)
  line L8 (17.6263, 14.8742) -> (-0.8337, -23.6158)
  line L9 (-4.0087, 18.0492) -> (-4.0087, -26.7908)
  line L10 (20.8013, 18.0492) -> (-4.0087, 18.0492)
  line L11 (20.8013, -26.7908) -> (20.8013, 18.0492)
  line L12 (-4.0087, -26.7908) -> (20.8013, -26.7908)
  point P2 (17.6963, 15.5831)
  point P6 (17.6963, 15.5831)
  point P4 (-0.9037, -24.3248)
  point P7 (-0.9037, -24.3248)
  point P3 (17.6963, -24.3248)
  point P8 (17.6963, -24.3248)
  point P5 (-0.9037, 15.5831)
  point P9 (-0.9037, 15.5831)
  point P10 (8.3963, -4.3708)
  point P15 (8.3963, -4.3708)
  point P13 (-0.8337, 14.8742)
  point P14 (17.6263, 14.8742)
  point P11 (17.6263, -23.6158)
  coincident P2 P6
  coincident P4 P7
  coincident P3 P8
  coincident P5 P9
  midpoint L1 P10
  horizontal L3
  perpendicular L3 L4
  parallel L3 L5
  parallel L4 L6
  coincident L7 P15
  coincident L8 P15
  coincident P10 P15
  dimension "d38" distance P13 P14 = 18.46
  dimension "d39" distance P11 P14 = 38.49
  dimension "d44" = -3.175 (= "( -1 / 8 ) * 1 in")
split "Split2"
split "Split3"
delete_face "DeleteFace3"
extrude "Extrude1" cut of existing geometry blind -33.02
delete_face "DeleteFace4"
extrude "Extrude2" cut of existing geometry blind -29.21
extrude "Extrude6" new body sketch "Sketch6" profile of L3 L4 L5 L6 L9 L12 L10 L11 along normal blind 28.4988
work_plane "WorkPlane3" AlongDistance -1.6
split "Split2"
sketch "Sketch7" plane through (0, 0, 26.4) normal (0, 0, 1) x axis (-1, 0, 0)
  line L1 (0.8337, -23.6158) -> (0.8337, 14.8742)
  line L2 (-17.6263, -23.6158) -> (0.8337, -23.6158)
  line L3 (-17.6263, 14.8742) -> (-17.6263, -23.6158)
  line L4 (0.8337, 14.8742) -> (-17.6263, 14.8742)
  line L5 (4.0087, -26.7908) -> (-20.8013, -26.7908)
  line L6 (4.0087, 18.0492) -> (4.0087, -26.7908)
  line L7 (-20.8013, 18.0492) -> (4.0087, 18.0492)
  line L8 (-20.8013, -26.7908) -> (-20.8013, 18.0492)
  line L9 (-20.8013, 6.1292) -> (4.0087, 6.1292)
  line L10 (-20.8013, -1.8708) -> (4.0087, -1.8708)
  circle C1 centre (-8.3963, 6.1292) radius 8.5
  circle C2 centre (-8.3963, 6.1292) radius 8.75
  point P12 (4.0087, 6.1292)
  point P13 (-20.8013, 6.1292)
  point P14 (4.0087, -1.8708)
  point P15 (-20.8013, -1.8708)
  coincident L6 P12
  coincident L8 P13
  perpendicular L8 L9
  coincident L6 P14
  coincident L8 P15
  perpendicular L8 L10
  dimension "d48" = 0.25
  dimension "d51" distance L9 L10 = 8
extrude "Extrude7" add sketch "Sketch7" profile of L1 L3 L4 C2 L10 against normal blind 26.8988
extrude "Extrude8" cut sketch "Sketch7" profile of L4 C2 against normal blind 38.1
offset_faces "OffsetFaces1" distance 0.75
fillet "Fillet3" radius 1.651
split "Split3"
remove_body "RemoveBody5"
mirror "Mirror1" mirrorStitchTolerance 0.1016
combine "Combine2"
component_from_bodies "Body->Comp1"
copy_paste_bodies "CutPasteBodies1"
mirror "Mirror1" mirrorStitchTolerance 0.1016
align "Align1"
extrude "Extrude1" add of existing geometry blind 6.35
extrude "Extrude9" new body of existing geometry blind 19.9898
copy_paste_bodies "CutPasteBodies2"
copy_paste "CutPaste3"
copy_paste_bodies "CutPasteBodies2"
sketch "Sketch8" plane through (0, 0, 19.9956) normal (0, 0, -1) x axis (1, 0, 0)
  line L1 (0.3963, -22.3708) -> (0.3963, -3.3708)
  line L2 (16.3963, -22.3708) -> (0.3963, -22.3708)
  line L3 (16.3963, -3.3708) -> (16.3963, -22.3708)
  line L4 (0.3963, -3.3708) -> (16.3963, -3.3708)
  line L5 (1.5713, -6.5458) -> (1.5713, -21.1958)
  line L6 (15.2213, -6.5458) -> (1.5713, -6.5458)
  line L7 (15.2213, -21.1958) -> (15.2213, -6.5458)
  line L8 (1.5713, -21.1958) -> (15.2213, -21.1958)
  line L9 (-4.0087, 18.0492) -> (20.8013, 18.0492)
  line L10 (-4.0087, -26.7908) -> (-4.0087, 18.0492)
  line L11 (20.8013, -26.7908) -> (-4.0087, -26.7908)
  line L12 (20.8013, 18.0492) -> (20.8013, -26.7908)
  line L13 (16.8763, -22.8658) -> (16.8763, -3.2059)
  line L14 (-0.0837, -22.8658) -> (16.8763, -22.8658)
  line L15 (-0.0837, -3.2059) -> (-0.0837, -22.8658)
  circle C1 centre (8.3963, -14.6208) radius 8
  circle C2 centre (8.3963, -14.6208) radius 8
  arc A1 centre (8.3963, 6.1292) radius 8.75 clockwise from (1.4656, 0.788) to (15.327, 0.788)
  arc A2 centre (16.6347, -0.2198) radius 1.651 clockwise from (15.93, -1.7129) to (15.327, 0.788)
  arc A3 centre (15.2253, -3.2059) radius 1.651 clockwise from (15.93, -1.7129) to (16.8763, -3.2059)
  arc A4 centre (1.5673, -3.2059) radius 1.651 clockwise from (-0.0837, -3.2059) to (0.8626, -1.7129)
  arc A5 centre (0.1579, -0.2198) radius 1.651 clockwise from (1.4656, 0.788) to (0.8626, -1.7129)
  circle C3 centre (8.3963, 6.1292) radius 8.5
  circle C4 centre (8.3963, 6.1292) radius 8.75
  dimension "d72" = 0.25
extrude "Extrude10" new body sketch "Sketch8" profile of L1 L2 L3 L4 L5 L6 L7 L8 C1 C2 A2 A3 L13 L14 L15 A4 A5 C4 along normal blind 5.0038
sketch "Sketch9" plane through (0, 0, 14.9918) normal (0, 0, -1) x axis (1, 0, 0)
  line L1 (-0.0837, -22.8658) -> (-0.0837, -3.2059)
  line L2 (16.8763, -22.8658) -> (-0.0837, -22.8658)
  line L3 (16.8763, -3.2059) -> (16.8763, -22.8658)
  circle C1 centre (8.3963, -14.6208) radius 8
  arc A1 centre (15.2253, -3.2059) radius 1.651 clockwise from (15.93, -1.7129) to (16.8763, -3.2059)
  arc A2 centre (16.6347, -0.2198) radius 1.651 clockwise from (15.93, -1.7129) to (15.327, 0.788)
  arc A3 centre (8.3963, 6.1292) radius 8.75 clockwise from (15.327, 0.788) to (1.4656, 0.788)
  arc A4 centre (0.1579, -0.2198) radius 1.651 clockwise from (1.4656, 0.788) to (0.8626, -1.7129)
  arc A5 centre (1.5673, -3.2059) radius 1.651 clockwise from (-0.0837, -3.2059) to (0.8626, -1.7129)
  arc A6 centre (8.3963, 6.1292) radius 8.75 clockwise from (15.327, 0.788) to (1.4656, 0.788)
  arc A7 centre (8.3963, 6.1292) radius 11.1625 clockwise from (17.2379, -0.6847) to (-0.4452, -0.6847)
  dimension "d73" = 2.4125 (= "0.125 in - 0.0300196850393694 in")
extrude "Extrude11" add sketch "Sketch9" profile of A1 A2 A3 A4 A5 A6 A7 along normal blind 15.4906
combine "Combine3"
delete_face "DeleteFace1"
delete_face "DeleteFace2"
fillet "Fillet1" radius 4.7625
sketch "Sketch10" plane through (0, 0, 8.3168) normal (0, 0, -1) x axis (1, 0, 0)
  circle C1 centre (8.3963, -14.6208) radius 4
  circle C2 centre (8.3963, -14.6208) radius 8
  circle C3 centre (8.3963, -14.6208) radius 9.5875
  dimension "d78" = 1.5875 (= "( 1 / 16 ) * 1 in")
extrude "Extrude7" cut sketch "Sketch10" along normal blind 15.24 and against normal blind 6.6802
extrude "Extrude8" add of existing geometry blind 0.0052 (= "2.047E-04 in")
sketch "Sketch11" plane through (0, 0, 14.9918) normal (0, 0, -1) x axis (1, 0, 0)
  line L1 (16.8763, -22.8658) -> (13.2892, -22.8658)
  line L2 (16.8763, -19.0941) -> (16.8763, -22.8658)
  line L3 (16.8763, -9.3559) -> (16.8763, -10.1476)
  line L4 (-0.0837, -10.1476) -> (-0.0837, -9.3559)
  line L5 (-0.0837, -22.8658) -> (-0.0837, -19.0941)
  line L6 (3.5034, -22.8658) -> (-0.0837, -22.8658)
  circle C1 centre (8.3963, -14.6208) radius 8
  arc A1 centre (8.3963, -14.6208) radius 9.5875 clockwise from (16.8763, -10.1476) to (16.8763, -19.0941)
  arc A2 centre (12.1138, -9.3559) radius 4.7625 clockwise from (11.0021, -4.7249) to (16.8763, -9.3559)
  arc A3 centre (8.3963, 6.1292) radius 11.1625 clockwise from (11.0021, -4.7249) to (5.7906, -4.7249)
  arc A4 centre (4.6788, -9.3559) radius 4.7625 clockwise from (-0.0837, -9.3559) to (5.7906, -4.7249)
  arc A5 centre (8.3963, -14.6208) radius 9.5875 clockwise from (-0.0837, -19.0941) to (-0.0837, -10.1476)
  arc A6 centre (8.3963, -14.6208) radius 9.5875 clockwise from (13.2892, -22.8658) to (3.5034, -22.8658)
  circle C2 centre (8.3963, -14.6208) radius 9.5875
  dimension "d85" = 1.5875 (= "( 1 / 16 ) * 1 in")
extrude "Extrude9" add sketch "Sketch11" profile of L1 L2 L3 A2 A3 A4 L4 L5 L6 C2 along normal blind 15.494
extrude "Extrude10" cut of existing geometry blind -0.0034 (= "-1.339E-04 in")
extrude "Extrude3" cut of existing geometry blind -0.508
extrude "Extrude11" cut of existing geometry blind -0.508
extrude "Extrude4" cut of existing geometry blind -1
offset_faces "OffsetFaces1" distance 1.5875 (= "( 1 / 16 ) * 1 in")
split "Split2"
delete_face "DeleteFace3"
combine "Combine4"
split "Split3"
sketch "Sketch12" plane through (0, 0, 4.8168) normal (0, 0, 1) x axis (-1, 0, 0)
  line L1 (-4.6463, -6.3208) -> (-1.1463, -9.8208)
  line L2 (-12.1463, -6.3208) -> (-4.6463, -6.3208)
  line L3 (-15.6463, -9.8208) -> (-12.1463, -6.3208)
  line L4 (-15.6463, -13.7917) -> (-15.6463, -9.8208)
  line L5 (-15.6463, -19.8208) -> (-15.6463, -15.45)
  line L6 (-1.1463, -15.45) -> (-1.1463, -19.8208)
  line L7 (-1.1463, -9.8208) -> (-1.1463, -13.7917)
  line L8 (-12.1463, -6.3208) -> (-15.6463, -9.8208)
  line L9 (-4.6463, -6.3208) -> (-12.1463, -6.3208)
  line L10 (-4.6463, -6.3208) -> (-1.1463, -9.8208)
  line L11 (-15.6463, -9.8208) -> (-15.6463, -19.8208)
  line L12 (-1.1463, -9.8208) -> (-1.1463, -19.8208)
  line L13 (-0.8963, -9.7173) -> (-0.8963, -19.8925)
  line L14 (-4.5428, -6.0708) -> (-0.8963, -9.7173)
  line L15 (-4.5428, -6.0708) -> (-12.2499, -6.0708)
  line L16 (-12.2499, -6.0708) -> (-15.8963, -9.7173)
  line L17 (-15.8963, -9.7173) -> (-15.8963, -19.8925)
  arc A1 centre (-14.3963, -14.6208) radius 1.5 clockwise from (-15.6463, -13.7917) to (-15.6463, -15.45)
  arc A2 centre (-8.3963, -15.2505) radius 8.5703 clockwise from (-1.1463, -19.8208) to (-15.6463, -19.8208)
  arc A3 centre (-2.3963, -14.6208) radius 1.5 clockwise from (-1.1463, -15.45) to (-1.1463, -13.7917)
  arc A4 centre (-8.3963, -15.2505) radius 8.5703 clockwise from (-1.1463, -19.8208) to (-15.6463, -19.8208)
  arc A5 centre (-8.3963, -15.2505) radius 8.8203 clockwise from (-0.8963, -19.8925) to (-15.8963, -19.8925)
  circle C1 centre (-8.3963, -14.6208) radius 9.5875
  point P15 (-15.6463, -19.8208)
  point P22 (-15.6463, -19.8208)
  point P18 (-15.6463, -9.8208)
  point P23 (-15.6463, -9.8208)
  point P16 (-1.1463, -19.8208)
  point P24 (-1.1463, -19.8208)
  point P21 (-1.1463, -9.8208)
  point P25 (-1.1463, -9.8208)
  coincident P15 P22
  coincident P18 P23
  coincident P16 P24
  coincident P21 P25
  dimension "d97" = 0.25
extrude "Extrude12" add sketch "Sketch12" profile of A5 L13 L14 L15 L16 L17 C1 against normal blind 4.8006
extrude "Extrude13" add of existing geometry blind 0.007 (= "2.756E-04 in")
split "Split4"
delete_face "DeleteFace4"
delete_face "DeleteFace5"
combine "Combine5"
extrude "Extrude14" add of existing geometry blind 1.4986
extrude "Extrude15" add of existing geometry blind 0.0014 (= "5.512E-05 in")
sketch "Sketch13" plane through (0, 0, 6.3168) normal (0, 0, 1) x axis (-1, 0, 0)
  line L1 (-15.8963, -9.7173) -> (-15.8963, -19.8925)
  line L2 (-12.2499, -6.0708) -> (-15.8963, -9.7173)
  line L3 (-4.5428, -6.0708) -> (-12.2499, -6.0708)
  line L4 (-0.8963, -9.7173) -> (-4.5428, -6.0708)
  line L5 (-0.8963, -19.8925) -> (-0.8963, -9.7173)
  line L6 (5.5962, 19.6367) -> (5.5962, -28.3783)
  line L7 (-22.3888, 19.6367) -> (5.5962, 19.6367)
  line L8 (-22.3888, -28.3783) -> (-22.3888, 19.6367)
  line L9 (5.5962, -28.3783) -> (-22.3888, -28.3783)
  line L10 (-3.6338, -52.7208) -> (-13.1588, -52.7208)
  line L11 (-3.6338, 23.4792) -> (-3.6338, -52.7208)
  line L12 (-13.1588, 23.4792) -> (-3.6338, 23.4792)
  line L13 (-13.1588, -52.7208) -> (-13.1588, 23.4792)
  line L14 (-3.6338, 23.4792) -> (-13.1588, -52.7208)
  line L15 (-13.1588, 23.4792) -> (-3.6338, -52.7208)
  arc A1 centre (-8.3963, -15.2505) radius 8.8203 clockwise from (-0.8963, -19.8925) to (-15.8963, -19.8925)
  circle C1 centre (-8.3963, 6.1292) radius 8.75
  circle C2 centre (-8.3963, -14.6208) radius 4
  point P19 (-8.3963, -14.6208)
  point P14 (-8.3963, -14.6208)
  point P15 (-13.1588, -52.7208)
  point P16 (-3.6338, -52.7208)
  point P18 (-13.1588, 23.4792)
  horizontal L10
  perpendicular L10 L11
  parallel L10 L12
  parallel L11 L13
  coincident L14 P19
  coincident L15 P19
  coincident P14 P19
  dimension "d106" distance P15 P16 = 9.525
  dimension "d107" distance P15 P18 = 76.2
extrude "Extrude16" cut sketch "Sketch13" profile of A1 L9 L11 L13 against normal blind 3.2004
extrude "Extrude17" cut sketch "Sketch13" profile of L7 C1 L11 L13 against normal blind 5.3086
extrude "Extrude18" cut of existing geometry blind -0.0002 (= "-7.873E-06 in")
extrude "Extrude19" add of existing geometry blind 0.0004 (= "1.574E-05 in")
combine "Combine1"
offset_faces "OffsetFaces2" distance 0.7937 (= "( 1 / 32 ) * 1 in")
